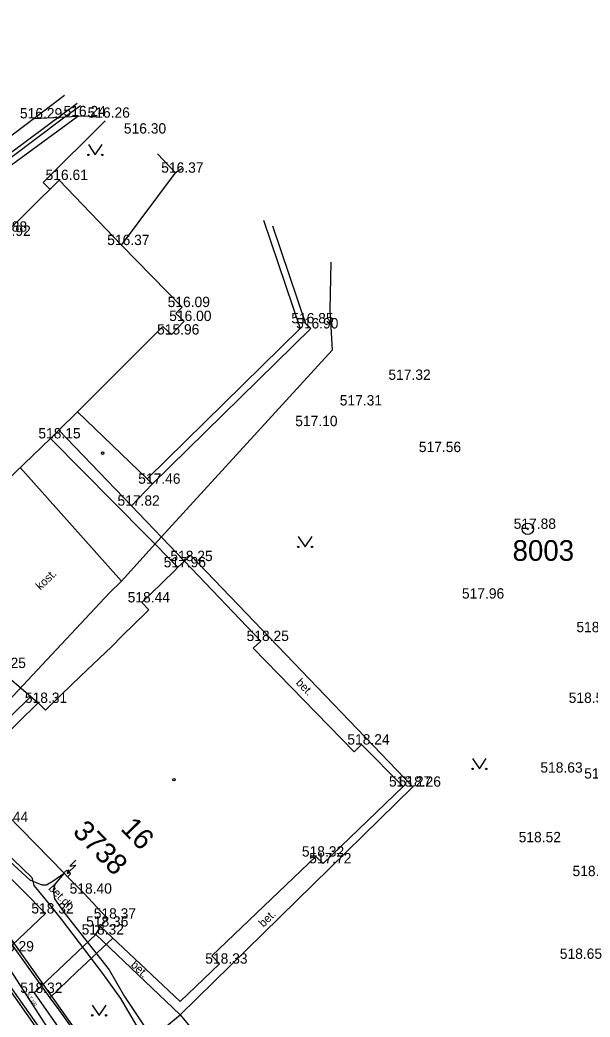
# Model space of a CAD drawing. Extents: x -668867 to -667827, y -1131943 to -1131019.
# Drawn here: x -668520.1 to -668478.8, y -1131166 to -1131093.7 of the extents above; entities that cross this region are included whole.
import ezdxf

# ---------------------------------------------------------------- set-up
doc = ezdxf.new("R2010")
doc.units = 0
for name, color, linetype in [('G_Bod_tecka', 7, 'Continuous'), ('G_Bod_vyska', 7, 'Continuous'), ('G_Bodove_pole', 7, 'Continuous'), ('G_Budovy-znacky', 7, 'Continuous'), ('G_Budovy_Objekty', 7, 'Continuous'), ('G_Budovy_vstupy', 7, 'Continuous'), ('G_Cesty_Schody', 7, 'Continuous'), ('G_Cisla_orientacni', 7, 'Continuous'), ('G_Cisla_popisna', 7, 'Continuous'), ('G_Plochy_zpevnene', 7, 'Continuous'), ('G_Ploty', 7, 'Continuous'), ('G_Ploty_vstupy', 7, 'Continuous'), ('G_Popisy_povrchu', 7, 'Continuous'), ('G_Site-Rozvadece', 7, 'Continuous'), ('G_Z_ELsilove_podz_kotovane', 7, 'Continuous'), ('G_Z_PLYNY_podz_geodeticky', 7, 'Continuous'), ('G_Z_SPOJE_podz_geodeticky', 7, 'Continuous'), ('G_Z_SPOJE_podz_kotovane', 7, 'Continuous'), ('G_Z_SPOJE_podz_priblizne', 7, 'Continuous'), ('G_Z_VODA_podz_kotovane', 7, 'Continuous'), ('G_Zelen-okraj', 7, 'Continuous'), ('G_Zelen-Znacky', 7, 'Continuous'), ('Vrstva 27', 7, 'Continuous'), ('Vrstva 4', 7, 'Continuous')]:
    doc.layers.add(name, color=color, linetype=linetype)

msp = doc.modelspace()

# ---------------------------------------------------------------- linework, layer by layer
at = {"layer": 'G_Bod_tecka'}
for p, q in [((-668519.09, -1131100.84), (-668519.09, -1131100.84)), ((-668515.93, -1131100.68), (-668515.93, -1131100.68)), ((-668517.28, -1131105.31), (-668517.28, -1131105.31)), ((-668508.84, -1131104.78), (-668508.84, -1131104.78)), ((-668512.76, -1131110.03), (-668512.76, -1131110.03)), ((-668508.35, -1131114.53), (-668508.35, -1131114.53)), ((-668508.22, -1131115.54), (-668508.22, -1131115.54)), ((-668499.4, -1131115.71), (-668499.4, -1131115.71)), ((-668499.03, -1131116.08), (-668499.03, -1131116.08)), ((-668509.14, -1131116.52), (-668509.14, -1131116.52)), ((-668492.37, -1131119.81), (-668492.37, -1131119.81)), ((-668495.96, -1131121.67), (-668495.96, -1131121.67)), ((-668499.25, -1131123.17), (-668499.25, -1131123.17)), ((-668517.91, -1131124.06), (-668517.91, -1131124.06)), ((-668490.16, -1131125.05), (-668490.16, -1131125.05)), ((-668510.51, -1131127.35), (-668510.51, -1131127.35)), ((-668512.04, -1131128.94), (-668512.04, -1131128.94)), ((-668483.28, -1131130.62), (-668483.28, -1131130.62)), ((-668508.66, -1131133.41), (-668508.66, -1131133.41)), ((-668508.19, -1131132.96), (-668508.19, -1131132.96)), ((-668487.02, -1131135.68), (-668487.02, -1131135.68)), ((-668511.29, -1131135.96), (-668511.29, -1131135.96)), ((-668502.66, -1131138.76), (-668502.66, -1131138.76)), ((-668518.81, -1131143.25), (-668518.81, -1131143.25)), ((-668479.29, -1131143.25), (-668479.29, -1131143.25)), ((-668495.35, -1131146.27), (-668495.35, -1131146.27)), ((-668481.33, -1131148.31), (-668481.33, -1131148.31)), ((-668492.33, -1131149.32), (-668492.33, -1131149.32)), ((-668491.61, -1131149.33), (-668491.61, -1131149.33)), ((-668482.92, -1131153.36), (-668482.92, -1131153.36)), ((-668498.65, -1131154.4), (-668498.65, -1131154.4)), ((-668498.12, -1131154.89), (-668498.12, -1131154.89)), ((-668479, -1131155.82), (-668479, -1131155.82)), ((-668515.48, -1131157.09), (-668515.48, -1131157.09)), ((-668518.28, -1131158.53), (-668518.28, -1131158.53)), ((-668513.75, -1131158.9), (-668513.75, -1131158.9)), ((-668514.29, -1131159.48), (-668514.29, -1131159.48)), ((-668514.63, -1131160.06), (-668514.63, -1131160.06)), ((-668505.66, -1131162.17), (-668505.66, -1131162.17)), ((-668479.92, -1131161.82), (-668479.92, -1131161.82)), ((-668519.09, -1131164.29), (-668519.09, -1131164.29))]:
    msp.add_line(p, q, dxfattribs=at)
at = {"layer": 'G_Bodove_pole'}
for radius in [0.412, 0.05]:
    msp.add_circle((-668483.28, -1131130.62), radius, dxfattribs=at)
at = {"layer": 'G_Budovy-znacky'}
for centre in [(-668514.13, -1131125.13), (-668508.96, -1131148.81)]:
    msp.add_circle(centre, 0.0875, dxfattribs=at)
at = {"layer": 'G_Budovy_Objekty'}
for p, q in [((-668521.37, -1131109.36), (-668517.28, -1131105.31)), ((-668517.28, -1131105.31), (-668512.76, -1131110.03)), ((-668508.35, -1131114.53), (-668512.76, -1131110.03)), ((-668508.35, -1131114.53), (-668508.81, -1131114.99)), ((-668508.81, -1131114.99), (-668508.22, -1131115.54)), ((-668509.76, -1131115.93), (-668515.96, -1131122.12)), ((-668509.76, -1131115.93), (-668509.14, -1131116.52)), ((-668509.14, -1131116.52), (-668508.22, -1131115.54)), ((-668515.96, -1131122.12), (-668517.3, -1131123.45)), ((-668515.96, -1131122.12), (-668510.89, -1131126.98)), ((-668517.3, -1131123.45), (-668517.91, -1131124.06)), ((-668517.3, -1131123.45), (-668512.04, -1131128.94)), ((-668526.63, -1131132.44), (-668517.91, -1131124.06)), ((-668510.89, -1131126.98), (-668510.51, -1131127.35)), ((-668512.04, -1131128.94), (-668510.51, -1131127.35)), ((-668508.92, -1131133.66), (-668508.66, -1131133.41)), ((-668508.66, -1131133.41), (-668508.19, -1131132.96)), ((-668502.66, -1131138.76), (-668508.19, -1131132.96)), ((-668511.29, -1131135.96), (-668510.64, -1131135.33)), ((-668510.77, -1131136.5), (-668511.29, -1131135.96)), ((-668510.77, -1131136.5), (-668510.98, -1131136.7)), ((-668512.7, -1131138.38), (-668513.49, -1131139.19)), ((-668503.2, -1131139.27), (-668502.66, -1131138.76)), ((-668503.2, -1131139.27), (-668495.88, -1131146.8)), ((-668515.24, -1131140.84), (-668516.34, -1131141.9)), ((-668524.57, -1131148.88), (-668518.81, -1131143.25)), ((-668518.28, -1131143.78), (-668518.81, -1131143.25)), ((-668518.07, -1131143.58), (-668518.28, -1131143.78)), ((-668495.88, -1131146.8), (-668495.35, -1131146.27)), ((-668495.35, -1131146.27), (-668492.33, -1131149.32)), ((-668492.33, -1131149.32), (-668498.12, -1131154.89)), ((-668516.95, -1131155.58), (-668521.05, -1131151.37)), ((-668498.65, -1131154.4), (-668506.2, -1131161.61)), ((-668498.12, -1131154.89), (-668498.65, -1131154.4)), ((-668516.67, -1131155.87), (-668516.95, -1131155.58)), ((-668515.48, -1131157.09), (-668516.67, -1131155.87)), ((-668513.75, -1131158.9), (-668514.29, -1131159.48)), ((-668514.24, -1131158.4), (-668513.75, -1131158.9)), ((-668508.51, -1131164.92), (-668514.29, -1131159.48)), ((-668506.2, -1131161.61), (-668505.66, -1131162.17)), ((-668505.66, -1131162.17), (-668508.51, -1131164.92))]:
    msp.add_line(p, q, dxfattribs=at)
at = {"layer": 'G_Budovy_vstupy'}
for p, q in [((-668508.92, -1131133.66), (-668510.64, -1131135.33)), ((-668510.98, -1131136.7), (-668512.7, -1131138.38)), ((-668513.49, -1131139.19), (-668515.24, -1131140.84)), ((-668516.34, -1131141.9), (-668518.07, -1131143.58)), ((-668515.48, -1131157.09), (-668514.24, -1131158.4))]:
    msp.add_line(p, q, dxfattribs=at)
at = {"layer": 'G_Cesty_Schody'}
msp.add_line((-668519.09, -1131100.84), (-668515.93, -1131100.68), dxfattribs=at)
for points in [[(-668519.34, -1131142.79), (-668518.81, -1131143.25)], [(-668514.63, -1131160.06), (-668514.29, -1131159.48)]]:
    msp.add_lwpolyline(points, dxfattribs=at)
at = {"layer": 'G_Plochy_zpevnene'}
msp.add_line((-668524.31, -1131106.77), (-668515.93, -1131100.68), dxfattribs=at)
for points in [[(-668516.904, -1131099.173), (-668519.09, -1131100.84), (-668528.91, -1131108.28), (-668538.73, -1131115.7)], [(-668514.35, -1131100.772), (-668515.05, -1131100.7), (-668515.93, -1131100.68)], [(-668508.84, -1131104.78), (-668510.153, -1131103.399)], [(-668507.76, -1131132.54), (-668508.19, -1131132.96)], [(-668507.76, -1131132.54), (-668491.61, -1131149.33)], [(-668528.51, -1131143.03), (-668526.93, -1131141.99), (-668524.42, -1131140.62), (-668523.66, -1131140.38), (-668522.89, -1131140.34), (-668522.28, -1131140.44), (-668521.74, -1131140.72), (-668520.54, -1131141.75), (-668519.34, -1131142.79)], [(-668524.9, -1131148.22), (-668519.34, -1131142.79)], [(-668491.61, -1131149.33), (-668508.51, -1131165.89)], [(-668518.28, -1131158.53), (-668523.26, -1131153.5)], [(-668521.17, -1131161.28), (-668518.28, -1131158.53)], [(-668519.09, -1131164.29), (-668514.63, -1131160.06)], [(-668508.51, -1131165.89), (-668514.63, -1131160.06)], [(-668519.09, -1131164.29), (-668516.8, -1131167.57), (-668514.52, -1131170.85), (-668512.32, -1131173.99), (-668510.12, -1131177.12), (-668504.98, -1131184.32), (-668499.66, -1131191.4), (-668495.33, -1131196.99), (-668490.99, -1131202.58)]]:
    msp.add_lwpolyline(points, dxfattribs=at)
at = {"layer": 'G_Ploty'}
for p, q in [((-668512.76, -1131110.03), (-668508.84, -1131104.78)), ((-668502.451, -1131108.22), (-668499.79, -1131116.09)), ((-668501.798, -1131108.629), (-668499.4, -1131115.71)), ((-668499.79, -1131116.09), (-668510.89, -1131126.98)), ((-668517.91, -1131124.06), (-668508.66, -1131133.41)), ((-668512.04, -1131128.94), (-668508.19, -1131132.96))]:
    msp.add_line(p, q, dxfattribs=at)
msp.add_lwpolyline([(-668510.51, -1131127.35), (-668499.03, -1131116.08), (-668499.4, -1131115.71)], dxfattribs=at)
at = {"layer": 'G_Ploty_vstupy'}
msp.add_line((-668508.388, -1131104.504), (-668508.84, -1131104.78), dxfattribs=at)
at = {"layer": 'G_Site-Rozvadece'}
for p, q in [((-668516.073, -1131155.011), (-668516.7, -1131155.621)), ((-668516.068, -1131154.656), (-668516.516, -1131155.093)), ((-668516.516, -1131155.093), (-668516.073, -1131155.011)), ((-668516.73, -1131155.38), (-668516.95, -1131155.58)), ((-668516.45, -1131155.66), (-668516.73, -1131155.38)), ((-668516.601, -1131155.371), (-668516.7, -1131155.621)), ((-668516.7, -1131155.621), (-668516.448, -1131155.529)), ((-668516.67, -1131155.87), (-668516.45, -1131155.66))]:
    msp.add_line(p, q, dxfattribs=at)
at = {"layer": 'G_Z_ELsilove_podz_kotovane'}
for points in [[(-668555.398, -1131094.402), (-668552.424, -1131100.994), (-668549.819, -1131105.896), (-668549.036, -1131109.044), (-668543.513, -1131123.011), (-668538.77, -1131133.046), (-668533.966, -1131143.005), (-668533.886, -1131143.112), (-668529.079, -1131151.328), (-668522.184, -1131161.928), (-668516.261, -1131170.305), (-668508.028, -1131181.583), (-668500.536, -1131191.955), (-668492.492, -1131202.47), (-668484.337, -1131212.694), (-668478.332, -1131220.418)], [(-668556.493, -1131095.145), (-668554.122, -1131100.103), (-668548.87, -1131109.379), (-668543.078, -1131121.886), (-668542.515, -1131122.204), (-668542.111, -1131122.06), (-668541.748, -1131121.675), (-668541.426, -1131121.211), (-668539.241, -1131119.33), (-668532.251, -1131112.431), (-668526.488, -1131107.968), (-668516.979, -1131100.808), (-668515.738, -1131099.903)], [(-668515.975, -1131099.754), (-668517.114, -1131100.593), (-668526.709, -1131107.733), (-668532.411, -1131112.155), (-668539.445, -1131119.017), (-668541.629, -1131121.118), (-668541.933, -1131121.431), (-668542.228, -1131121.662), (-668542.512, -1131121.611), (-668542.843, -1131121.448), (-668547.35, -1131112.191), (-668548.24, -1131109.636), (-668550.9, -1131105.378), (-668553.911, -1131100.051), (-668556.371, -1131095.062)], [(-668522.931, -1131152.878), (-668519.382, -1131156.103), (-668519.222, -1131156.166), (-668519.183, -1131156.181), (-668518.956, -1131156.269), (-668518.547, -1131156.443), (-668518.197, -1131156.441), (-668517.712, -1131156.151), (-668516.918, -1131155.614), (-668517.576, -1131156.377), (-668517.724, -1131156.828), (-668517.612, -1131157.463), (-668516.87, -1131158.53), (-668513.648, -1131162.618), (-668512.547, -1131164.552), (-668511.049, -1131166.81)], [(-668522.663, -1131152.674), (-668519.274, -1131155.919), (-668519.185, -1131156.172), (-668519.183, -1131156.181), (-668519.121, -1131156.492), (-668517.995, -1131157.866), (-668517.147, -1131158.939), (-668514.13, -1131162.894), (-668512.839, -1131164.7), (-668511.513, -1131166.968)]]:
    msp.add_lwpolyline(points, dxfattribs=at)
at = {"layer": 'G_Z_PLYNY_podz_geodeticky'}
for points in [[(-668513.946, -1131101.025), (-668518.45, -1131105.48), (-668517.96, -1131105.98)], [(-668529.76, -1131143.74), (-668524.16, -1131155.67), (-668491.6, -1131201.52), (-668457.62, -1131243.27), (-668455.9, -1131245.37), (-668427.25, -1131279.92), (-668424.99, -1131282.65)]]:
    msp.add_lwpolyline(points, dxfattribs=at)
at = {"layer": 'G_Z_SPOJE_podz_geodeticky'}
for points in [[(-668497.572, -1131111.275), (-668497.64, -1131114.72), (-668497.48, -1131117.66), (-668509.85, -1131131.19), (-668512.75, -1131134.42)], [(-668520.11, -1131126.17), (-668512.75, -1131134.42)], [(-668512.75, -1131134.42), (-668513.64, -1131135.27), (-668525.5, -1131147.94), (-668527.12, -1131149.82), (-668527.37, -1131150.63), (-668527.3, -1131151.61), (-668517.96, -1131164.64)], [(-668513.39, -1131160.31), (-668515.99, -1131162.77), (-668517.96, -1131164.64)], [(-668517.96, -1131164.64), (-668517.26, -1131165.59)], [(-668517.26, -1131165.59), (-668513.76, -1131170.49), (-668511.79, -1131173.43)]]:
    msp.add_lwpolyline(points, dxfattribs=at)
at = {"layer": 'G_Z_SPOJE_podz_kotovane'}
for points in [[(-668538.05, -1131107.48), (-668541.02, -1131108.79), (-668541.35, -1131109.82), (-668535.86, -1131115.82), (-668534.58, -1131115.3), (-668531.82, -1131117.98), (-668536.77, -1131123.07), (-668537.78, -1131123.05), (-668538.54, -1131123.66), (-668538.88, -1131123.92), (-668539.22, -1131123.89), (-668541.22, -1131123.43), (-668541.47, -1131123.37), (-668542.59, -1131124.18), (-668542.56, -1131126.14), (-668537.42, -1131137.13), (-668529.67, -1131150.9), (-668522.72, -1131161.47), (-668503.3, -1131189.1), (-668501.247, -1131191.625)], [(-668497.572, -1131111.275), (-668497.64, -1131114.72), (-668497.48, -1131117.66), (-668509.85, -1131131.19), (-668512.75, -1131134.42)], [(-668520.11, -1131126.17), (-668512.75, -1131134.42)], [(-668512.75, -1131134.42), (-668513.64, -1131135.27), (-668525.5, -1131147.94), (-668527.12, -1131149.82), (-668527.37, -1131150.63), (-668527.3, -1131151.61), (-668517.96, -1131164.64)], [(-668513.39, -1131160.31), (-668515.99, -1131162.77), (-668517.96, -1131164.64)], [(-668517.96, -1131164.64), (-668517.26, -1131165.59)], [(-668517.26, -1131165.59), (-668513.76, -1131170.49), (-668511.79, -1131173.43)]]:
    msp.add_lwpolyline(points, dxfattribs=at)
at = {"layer": 'G_Z_SPOJE_podz_priblizne'}
for points in [[(-668497.572, -1131111.275), (-668497.64, -1131114.72), (-668497.48, -1131117.66), (-668509.85, -1131131.19), (-668512.75, -1131134.42)], [(-668520.11, -1131126.17), (-668512.75, -1131134.42)], [(-668512.75, -1131134.42), (-668513.64, -1131135.27), (-668525.5, -1131147.94), (-668527.12, -1131149.82), (-668527.37, -1131150.63), (-668527.3, -1131151.61), (-668517.96, -1131164.64)], [(-668513.39, -1131160.31), (-668515.99, -1131162.77), (-668517.96, -1131164.64)], [(-668517.96, -1131164.64), (-668517.26, -1131165.59)], [(-668517.26, -1131165.59), (-668513.76, -1131170.49), (-668511.79, -1131173.43)]]:
    msp.add_lwpolyline(points, dxfattribs=at)
at = {"layer": 'G_Z_VODA_podz_kotovane'}
msp.add_lwpolyline([(-668554.356, -1131093.695), (-668553.39, -1131095.66), (-668547.53, -1131106.87), (-668547.37, -1131107.14), (-668535.16, -1131134.42), (-668524.68, -1131156.69), (-668524.68, -1131156.69), (-668514.04, -1131173.18), (-668502.91, -1131189.19), (-668501.17, -1131191.76), (-668498.15, -1131195.68), (-668493.12, -1131202.03), (-668493.02, -1131202.16), (-668492.31, -1131203.14)], dxfattribs=at)
at = {"layer": 'G_Zelen-okraj'}
for points in [[(-668514.52, -1131170.85), (-668508.51, -1131165.89)], [(-668508.51, -1131165.89), (-668504.25, -1131171)]]:
    msp.add_lwpolyline(points, dxfattribs=at)
at = {"layer": 'G_Zelen-Znacky'}
for p, q in [((-668515.16, -1131102.74), (-668514.66, -1131103.49)), ((-668514.66, -1131103.49), (-668514.16, -1131102.74)), ((-668499.93, -1131131.18), (-668499.43, -1131131.93)), ((-668499.43, -1131131.93), (-668498.93, -1131131.18)), ((-668487.29, -1131147.29), (-668486.79, -1131148.04)), ((-668486.79, -1131148.04), (-668486.29, -1131147.29)), ((-668514.88, -1131165.17), (-668514.38, -1131165.92)), ((-668514.38, -1131165.92), (-668513.88, -1131165.17))]:
    msp.add_line(p, q, dxfattribs=at)
for centre in [(-668515.16, -1131103.49), (-668514.16, -1131103.49), (-668499.93, -1131131.93), (-668498.93, -1131131.93), (-668487.29, -1131148.04), (-668486.29, -1131148.04), (-668514.88, -1131165.92), (-668513.88, -1131165.92)]:
    msp.add_circle(centre, 0.05, dxfattribs=at)
at = {"layer": 'Vrstva 27'}
msp.add_lwpolyline([(-668554.359, -1131093.697), (-668553.394, -1131095.659), (-668547.53, -1131106.872), (-668547.372, -1131107.14), (-668535.158, -1131134.419), (-668524.68, -1131156.688), (-668524.679, -1131156.689), (-668514.04, -1131173.182), (-668502.909, -1131189.194), (-668501.166, -1131191.758), (-668498.148, -1131195.679), (-668493.124, -1131202.026), (-668493.025, -1131202.162), (-668492.315, -1131203.139)], dxfattribs=at)

# ---------------------------------------------------------------- texts
at = {"layer": 'G_Bod_vyska'}
for s, p in [('516.29', (-668520.128, -1131100.84)), ('516.24', (-668516.966, -1131100.68)), ('516.26', (-668515.22, -1131100.79)), ('516.30', (-668512.588, -1131101.94)), ('516.61', (-668518.268, -1131105.31)), ('516.37', (-668509.876, -1131104.78)), ('516.88', (-668522.676, -1131109.06)), ('516.92', (-668522.408, -1131109.36)), ('516.37', (-668513.796, -1131110.03)), ('516.09', (-668509.41, -1131114.53)), ('516.00', (-668509.299, -1131115.54)), ('516.85', (-668500.436, -1131115.71)), ('516.90', (-668500.09, -1131116.08)), ('515.96', (-668510.178, -1131116.52)), ('517.32', (-668493.392, -1131119.81)), ('517.31', (-668496.921, -1131121.67)), ('517.10', (-668500.152, -1131123.17)), ('518.15', (-668518.791, -1131124.06)), ('517.56', (-668491.186, -1131125.05)), ('517.46', (-668511.546, -1131127.35)), ('517.82', (-668513.052, -1131128.94)), ('517.88', (-668484.302, -1131130.62)), ('517.96', (-668509.698, -1131133.41)), ('518.25', (-668509.212, -1131132.96)), ('517.96', (-668488.058, -1131135.68)), ('518.44', (-668512.312, -1131135.96)), ('518.45', (-668479.752, -1131138.12)), ('518.25', (-668503.682, -1131138.76)), ('518.25', (-668522.762, -1131140.72)), ('518.31', (-668519.771, -1131143.25)), ('518.57', (-668480.312, -1131143.25)), ('518.24', (-668496.372, -1131146.27)), ('518.63', (-668482.366, -1131148.31)), ('518.71', (-668479.191, -1131148.74)), ('518.27', (-668493.352, -1131149.32)), ('518.26', (-668492.646, -1131149.33)), ('518.44', (-668522.602, -1131151.9)), ('518.52', (-668483.942, -1131153.36)), ('518.32', (-668499.672, -1131154.4)), ('517.72', (-668499.142, -1131154.89)), ('518.70', (-668480.034, -1131155.82)), ('518.40', (-668516.524, -1131157.09)), ('518.32', (-668519.302, -1131158.53)), ('518.37', (-668514.772, -1131158.9)), ('518.36', (-668515.326, -1131159.48)), ('518.32', (-668515.652, -1131160.06)), ('518.29', (-668522.184, -1131161.28)), ('518.65', (-668480.956, -1131161.82)), ('518.33', (-668506.682, -1131162.17)), ('518.32', (-668520.112, -1131164.29))]:
    msp.add_text(s, height=0.75, dxfattribs=at).set_placement(p)
at = {"layer": 'G_Bodove_pole'}
msp.add_text('8003', height=1.5, dxfattribs=at).set_placement((-668484.383, -1131132.94))
at = {"layer": 'G_Cisla_orientacni'}
msp.add_text('16', height=1.5, rotation=314.23367, dxfattribs=at).set_placement((-668512.891, -1131152.43))
at = {"layer": 'G_Cisla_popisna'}
msp.add_text('3738', height=1.5, rotation=314.23367, dxfattribs=at).set_placement((-668516.368, -1131152.661))
at = {"layer": 'G_Popisy_povrchu'}
for s, rotation, p in [('kost.', 44.12223, (-668518.636, -1131135.107)), ('bet.', 314.19742, (-668500.145, -1131141.825)), ('bet.dl.', 313.61428, (-668518.099, -1131156.747)), ('bet.', 44.41252, (-668502.462, -1131159.567)), ('bet.', 316.41892, (-668512.133, -1131162.314))]:
    msp.add_text(s, height=0.6, rotation=rotation, dxfattribs=at).set_placement(p)
at = {"layer": 'Vrstva 4'}
msp.add_text('ŠLT 100', height=0.2194, rotation=302.83865, dxfattribs=at).set_placement((-668519.68, -1131164.31))

doc.saveas('drawing.dxf')
